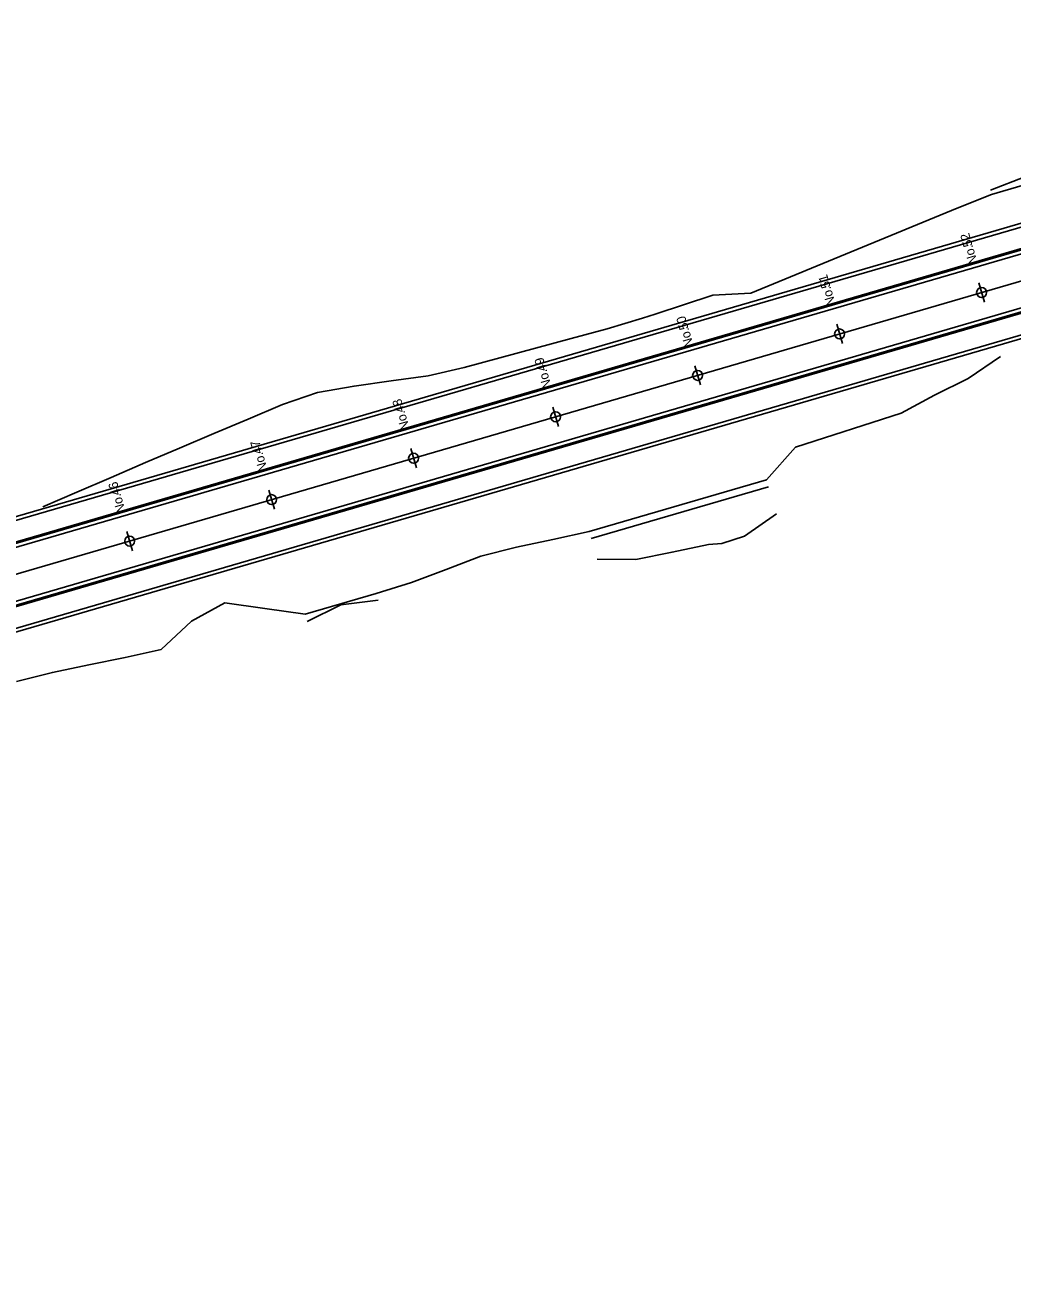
# Model space of a CAD drawing. Extents: x 46424 to 47578, y 10417 to 11548.
# Drawn here: x 46928.8 to 47062.3, y 10913.1 to 11080.9 of the extents above; entities that cross this region are included whole.
import ezdxf

# ---------------------------------------------------------------- set-up
doc = ezdxf.new("R2010")
doc.units = 0
for name, color, linetype in [('Default', 7, 'Continuous'), ('出典（地理院地図Vector）', 7, 'Continuous'), ('河川_人工水路(地下)（地理院地図Vector）', 7, 'Continuous'), ('現況_地形', 7, 'Continuous'), ('現況_地形_三角形', 7, 'Continuous'), ('現況_地形_三角形_頂点', 7, 'Continuous'), ('現況_地形_低い点', 7, 'Continuous'), ('現況_地形_単点標高', 7, 'Continuous'), ('現況_地形_等高線_マイナー', 7, 'Continuous'), ('等高線等深線_等高線_補助曲線通常部（地理院地図Vector）', 7, 'Continuous'), ('設計図面_測点 ラベル メジャー', 7, 'Continuous'), ('設計図面_測点 印 メジャー', 7, 'Continuous')]:
    doc.layers.add(name, color=color, linetype=linetype)

msp = doc.modelspace()

# ---------------------------------------------------------------- linework, layer by layer
at = {"layer": 'Default'}
for p, q in [((46606.99, 10913.06), (47182.22, 11080.85)), ((46773.73, 10961.69), (47084.04, 11052.21)), ((47058.19, 11044.67), (47058.19, 11044.67)), ((47038.99, 11039.07), (47038.99, 11039.07)), ((47019.79, 11033.47), (47019.79, 11033.47)), ((47000.59, 11027.87), (47000.59, 11027.87)), ((46981.39, 11022.27), (46981.39, 11022.27)), ((46962.19, 11016.67), (46962.19, 11016.67)), ((46942.99, 11011.07), (46942.99, 11011.07))]:
    msp.add_line(p, q, dxfattribs=at)
for centre in [(47058.19, 11044.67), (47038.99, 11039.07), (47019.79, 11033.47), (47000.59, 11027.87), (46981.39, 11022.27), (46962.19, 11016.67), (46942.99, 11011.07)]:
    msp.add_circle(centre, 0.675, dxfattribs=at)
at = {"layer": '出典（地理院地図Vector）'}
for points in [[(46772.89, 10969.26), (47081.94, 11059.41), (47084.89, 11060.27), (47089.68, 11061.67), (47093.92, 11062.92), (47094.47, 11063.08), (47099.24, 11064.49), (47104.01, 11065.92), (47105.84, 11066.48), (47108.76, 11067.36), (47113.5, 11068.83), (47117.69, 11070.14), (47118.23, 11070.32), (47122.94, 11071.83), (47127.64, 11073.38), (47129.44, 11073.99)], [(46777.09, 10954.86), (47086.14, 11045.01), (47089.09, 11045.87), (47093.9, 11047.28), (47098.16, 11048.53), (47098.71, 11048.69), (47103.52, 11050.12), (47108.34, 11051.56), (47110.19, 11052.12), (47113.15, 11053.02), (47117.96, 11054.51), (47122.23, 11055.85), (47122.78, 11056.02), (47127.58, 11057.57), (47132.39, 11059.15), (47134.24, 11059.77)]]:
    msp.add_lwpolyline(points, dxfattribs=at)
at = {"layer": '河川_人工水路(地下)（地理院地図Vector）'}
msp.add_line((46773.73, 10961.69), (47084.04, 11052.21), dxfattribs=at)
at = {"layer": '現況_地形'}
for points in [[(46774.01, 10965.42), (47083.06, 11055.57), (47086.01, 11056.43), (47090.81, 11057.84), (47095.05, 11059.08), (47095.6, 11059.24), (47100.38, 11060.66), (47105.16, 11062.09), (47107, 11062.65), (47109.93, 11063.54), (47114.69, 11065.01), (47118.9, 11066.33), (47119.44, 11066.5), (47124.18, 11068.03), (47128.9, 11069.58), (47130.72, 11070.2)], [(46774.01, 10965.43), (47083.06, 11055.58), (47086.01, 11056.44), (47090.8, 11057.84), (47095.05, 11059.09), (47095.6, 11059.25), (47100.38, 11060.67), (47105.16, 11062.1), (47107, 11062.66), (47109.93, 11063.55), (47114.69, 11065.02), (47118.9, 11066.34), (47119.44, 11066.51), (47124.18, 11068.04), (47128.9, 11069.59), (47130.72, 11070.2)], [(46775.97, 10958.7), (47085.02, 11048.85), (47087.97, 11049.71), (47092.77, 11051.12), (47097.03, 11052.37), (47097.58, 11052.53), (47102.38, 11053.95), (47107.18, 11055.39), (47109.03, 11055.95), (47111.98, 11056.85), (47116.77, 11058.33), (47121.02, 11059.66), (47121.56, 11059.83), (47126.35, 11061.37), (47131.12, 11062.95), (47132.96, 11063.56)], [(46775.98, 10958.69), (47085.03, 11048.84), (47087.97, 11049.7), (47092.78, 11051.11), (47097.03, 11052.36), (47097.58, 11052.52), (47102.38, 11053.94), (47107.18, 11055.38), (47109.04, 11055.94), (47111.98, 11056.84), (47116.78, 11058.32), (47121.02, 11059.65), (47121.57, 11059.82), (47126.35, 11061.36), (47131.12, 11062.94), (47132.96, 11063.55)]]:
    msp.add_lwpolyline(points, dxfattribs=at)
at = {"layer": '現況_地形_三角形'}
for points in [[(47059.37, 11058.49), (47064.05, 11060.29), (47080.3, 11065.03), (47083.25, 11065.89), (47088.04, 11067.29), (47092.27, 11068.53), (47092.81, 11068.69), (47097.57, 11070.1), (47102.32, 11071.52), (47104.15, 11072.07), (47107.05, 11072.96), (47111.76, 11074.41), (47115.92, 11075.72), (47116.46, 11075.89), (47121.13, 11077.39), (47125.78, 11078.93), (47127.57, 11079.53)], [(46931.23, 11015.69), (46935.85, 11017.69), (46940.48, 11019.68), (46945.11, 11021.67), (46949.74, 11023.64), (46954.38, 11025.61), (46959.01, 11027.56), (46963.65, 11029.51), (46968.38, 11031.16), (46973.34, 11032.01), (46978.34, 11032.72), (46983.35, 11033.4), (46988.23, 11034.55), (46993.05, 11035.86), (46997.88, 11037.16), (47002.71, 11038.46), (47007.55, 11039.74), (47012.33, 11041.2), (47014.04, 11041.76), (47021.84, 11044.31), (47026.97, 11044.56), (47054.86, 11056.09), (47059.53, 11057.93), (47080.58, 11064.07)]]:
    msp.add_lwpolyline(points, dxfattribs=at)
at = {"layer": '現況_地形_三角形_頂点'}
msp.add_line((47005.39, 11011.41), (47029.39, 11018.41), dxfattribs=at)
for points in [[(46927.69, 10992.09), (46932.55, 10993.31), (46937.46, 10994.33), (46942.37, 10995.34), (46947.26, 10996.43), (46951.36, 11000.25), (46955.84, 11002.72), (46961.28, 11001.96), (46966.71, 11001.17), (46976.31, 11003.97), (46981.09, 11005.46), (46985.78, 11007.24), (46990.47, 11009.01), (46995.31, 11010.26), (47000.22, 11011.29), (47005.11, 11012.37), (47029.11, 11019.37), (47033.04, 11023.76), (47047.32, 11028.37), (47051.83, 11030.78), (47056.38, 11033.04), (47060.72, 11036)], [(47006.21, 11008.61), (47011.43, 11008.58), (47016.34, 11009.59), (47021.26, 11010.59), (47023.08, 11010.76), (47026.14, 11011.72), (47030.46, 11014.74)], [(46966.99, 11000.21), (46971.55, 11002.45), (46976.57, 11003.08)]]:
    msp.add_lwpolyline(points, dxfattribs=at)
at = {"layer": '現況_地形_低い点'}
for points in [[(46773.87, 10965.9), (47082.92, 11056.05), (47085.87, 11056.91), (47090.67, 11058.32), (47094.91, 11059.56), (47095.46, 11059.72), (47100.24, 11061.14), (47105.02, 11062.57), (47106.86, 11063.13), (47109.79, 11064.02), (47114.54, 11065.49), (47118.75, 11066.81), (47119.29, 11066.98), (47124.02, 11068.5), (47128.74, 11070.06), (47130.56, 11070.67)], [(46776.11, 10958.22), (47085.16, 11048.37), (47088.11, 11049.23), (47092.91, 11050.64), (47097.17, 11051.89), (47097.72, 11052.05), (47102.52, 11053.47), (47107.33, 11054.91), (47109.18, 11055.47), (47112.13, 11056.37), (47116.92, 11057.85), (47121.17, 11059.18), (47121.72, 11059.36), (47126.5, 11060.9), (47131.28, 11062.47), (47133.12, 11063.09)]]:
    msp.add_lwpolyline(points, dxfattribs=at)
at = {"layer": '現況_地形_単点標高'}
for points in [[(46773.03, 10968.78), (47082.08, 11058.93), (47085.03, 11059.79), (47089.82, 11061.19), (47094.06, 11062.44), (47094.61, 11062.6), (47099.38, 11064.01), (47104.15, 11065.44), (47105.99, 11066), (47108.91, 11066.89), (47113.65, 11068.35), (47117.84, 11069.67), (47118.38, 11069.84), (47123.1, 11071.36), (47127.79, 11072.9), (47129.6, 11073.51)], [(46773.82, 10966.09), (47082.87, 11056.25), (47085.81, 11057.11), (47090.61, 11058.51), (47094.85, 11059.75), (47095.4, 11059.91), (47100.18, 11061.33), (47104.96, 11062.76), (47106.8, 11063.32), (47109.73, 11064.21), (47114.48, 11065.68), (47118.69, 11067), (47119.23, 11067.17), (47123.96, 11068.69), (47128.68, 11070.25), (47130.5, 11070.86)], [(46776.17, 10958.03), (47085.22, 11048.18), (47088.17, 11049.04), (47092.97, 11050.45), (47097.23, 11051.7), (47097.78, 11051.86), (47102.58, 11053.28), (47107.38, 11054.72), (47109.24, 11055.28), (47112.18, 11056.18), (47116.98, 11057.66), (47121.23, 11058.99), (47121.78, 11059.17), (47126.56, 11060.71), (47131.34, 11062.28), (47133.18, 11062.9)], [(46776.95, 10955.34), (47086, 11045.49), (47088.95, 11046.35), (47093.76, 11047.76), (47098.02, 11049.01), (47098.57, 11049.17), (47103.38, 11050.6), (47108.19, 11052.04), (47110.05, 11052.6), (47113, 11053.5), (47117.82, 11054.98), (47122.08, 11056.32), (47122.62, 11056.5), (47127.43, 11058.04), (47132.23, 11059.63), (47134.08, 11060.25)]]:
    msp.add_lwpolyline(points, dxfattribs=at)
at = {"layer": '現況_地形_等高線_マイナー'}
for points in [[(46773.87, 10965.92), (47082.92, 11056.07), (47085.86, 11056.93), (47090.66, 11058.33), (47094.9, 11059.58), (47095.45, 11059.74), (47100.23, 11061.16), (47105.01, 11062.59), (47106.85, 11063.14), (47109.78, 11064.04), (47114.54, 11065.5), (47118.74, 11066.83), (47119.28, 11067), (47124.02, 11068.52), (47128.74, 11070.08), (47130.55, 11070.69)], [(46776.12, 10958.2), (47085.17, 11048.35), (47088.12, 11049.21), (47092.92, 11050.62), (47097.18, 11051.87), (47097.72, 11052.03), (47102.53, 11053.45), (47107.33, 11054.89), (47109.18, 11055.45), (47112.13, 11056.35), (47116.93, 11057.83), (47121.17, 11059.16), (47121.72, 11059.34), (47126.51, 11060.88), (47131.28, 11062.45), (47133.13, 11063.07)]]:
    msp.add_lwpolyline(points, dxfattribs=at)
at = {"layer": '等高線等深線_等高線_補助曲線通常部（地理院地図Vector）'}
msp.add_line((46773.73, 10961.69), (47084.04, 11052.21), dxfattribs=at)
at = {"layer": '設計図面_測点 印 メジャー'}
for p, q in [((47057.81, 11045.97), (47058.57, 11043.38)), ((47038.61, 11040.37), (47039.37, 11037.78)), ((47019.41, 11034.77), (47020.17, 11032.17)), ((47000.21, 11029.17), (47000.97, 11026.57)), ((46981.01, 11023.57), (46981.77, 11020.97)), ((46961.81, 11017.96), (46962.57, 11015.37)), ((46942.61, 11012.36), (46943.37, 11009.77))]:
    msp.add_line(p, q, dxfattribs=at)

# ---------------------------------------------------------------- texts
at = {"layer": '設計図面_測点 ラベル メジャー'}
for s, p in [('52', (47056.99, 11051.03)), ('No.', (47057.67, 11048.69)), ('51', (47037.79, 11045.43)), ('No.', (47038.47, 11043.09)), ('50', (47018.59, 11039.82)), ('No.', (47019.27, 11037.49)), ('49', (46999.39, 11034.22)), ('No.', (47000.07, 11031.89)), ('48', (46980.19, 11028.62)), ('No.', (46980.87, 11026.28)), ('47', (46960.99, 11023.02)), ('No.', (46961.67, 11020.68)), ('46', (46941.79, 11017.42)), ('No.', (46942.47, 11015.08))]:
    msp.add_text(s, height=1.25, rotation=106.2622, dxfattribs=at).set_placement(p)

doc.saveas('drawing.dxf')
